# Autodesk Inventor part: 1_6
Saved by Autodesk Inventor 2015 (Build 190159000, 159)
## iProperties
Created: 2015-01
Part Number: 1_6
Material: Rubber
Document SubType Name: Modeling
Designer: TODD D MILLER
Mass: 7.36649 g
Surface Area: 29.177 cm^2
Volume: 7.92095 cm^3
Density: 0.93 g/cm^3
Appearance: Rubber - Black - Version 1.1
Author: TODD D MILLER
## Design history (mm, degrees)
node "1_6.ipt1"
node "Imported1"
node "Base1"
